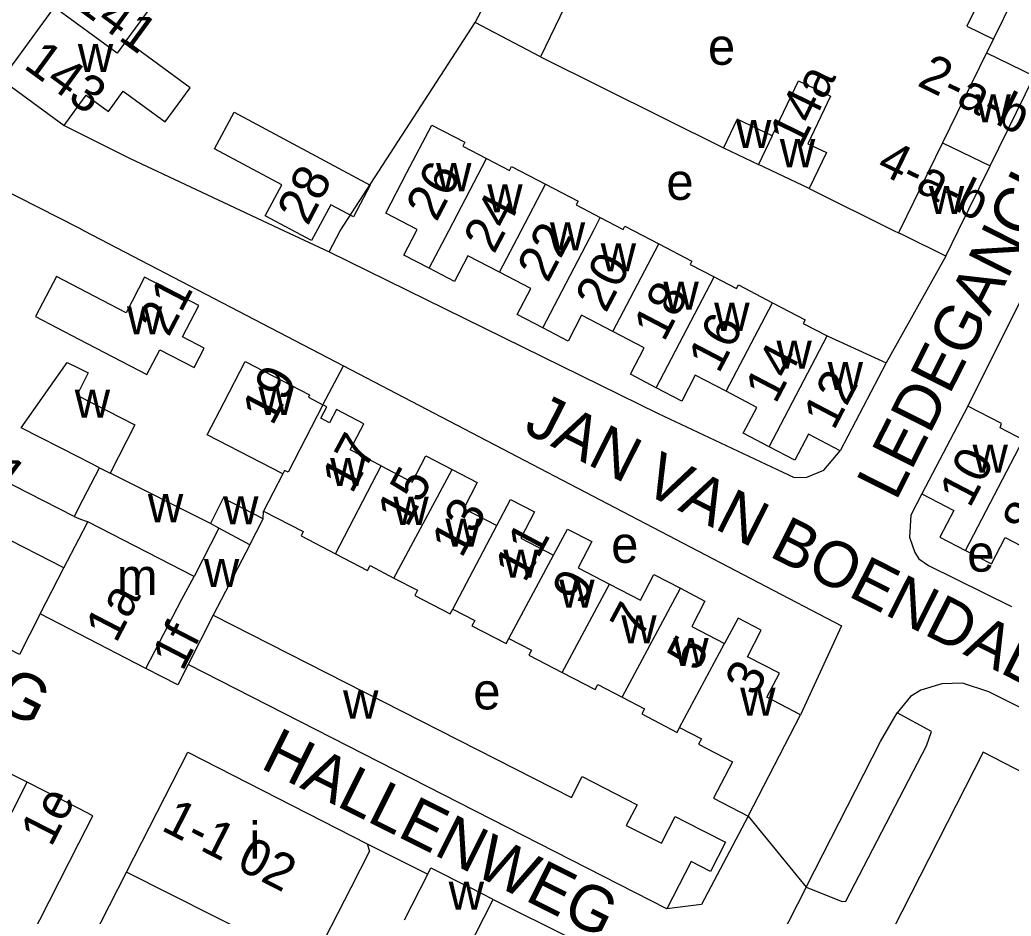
# Model space of a CAD drawing. Extents: x 159700 to 161346, y 381730 to 382922.
# Drawn here: x 160693.5 to 160801.9, y 382358.4 to 382456.4 of the extents above; entities that cross this region are included whole.
import ezdxf

# ---------------------------------------------------------------- set-up
doc = ezdxf.new("R2010")
doc.units = 0
for name, color, linetype in [('BLT_Basislijn', 7, 'Continuous'), ('BLT_Bebouwing', 7, 'Continuous'), ('BLT_Centroide', 7, 'Continuous'), ('BLT_Huisnummer', 7, 'Continuous'), ('BLT_Huisnummer_ tussenligend', 7, 'Continuous'), ('BLT_Huisnummer_reeks', 7, 'Continuous'), ('BLT_Huisnummer_zonder_bebouwing', 7, 'Continuous'), ('BLT_Onderverdeling_panden', 7, 'Continuous'), ('BLT_Plantopo', 7, 'Continuous'), ('BLT_Straatnaam', 7, 'Continuous'), ('BLT_Vlakafsluiter', 7, 'Continuous')]:
    doc.layers.add(name, color=color, linetype=linetype)

msp = doc.modelspace()

# ---------------------------------------------------------------- linework, layer by layer
at = {"layer": 'BLT_Basislijn'}
for p, q in [((160750.48, 382452.35), (160770.5, 382442.41)), ((160689.49, 382438.97), (160700, 382433.64)), ((160794.8, 382430.56), (160788.26, 382418.89)), ((160797.19, 382414.17), (160803.72, 382427.16)), ((160726.67, 382414.31), (160728.93, 382418.55)), ((160728.93, 382418.55), (160783.39, 382390.12)), ((160720.14, 382401.84), (160720.2, 382402.69)), ((160731.53, 382366.3), (160738.15, 382362.99)), ((160779.53, 382361.55), (160773.93, 382350.62)), ((160745.3, 382360.23), (160753.96, 382355.93))]:
    msp.add_line(p, q, dxfattribs=at)
for points in [[(160727.37, 382431.02), (160728.56, 382433.33), (160743.33, 382456.11)], [(160698.39, 382444.84), (160700, 382444.04)], [(160700, 382444.04), (160705.61, 382441.23), (160722.44, 382433.33), (160727.37, 382431.02)], [(160779.87, 382437.96), (160789.14, 382433.33), (160789.62, 382433.1)], [(160700, 382433.64), (160700.59, 382433.33), (160728.93, 382418.55)], [(160727.37, 382431.02), (160763.35, 382413.34), (160778.23, 382406.35), (160779.59, 382406.4), (160781.46, 382407.14), (160783.23, 382409.28)], [(160792.19, 382404.56), (160790.97, 382402.24), (160790.82, 382399.84), (160791.41, 382398.17), (160791.86, 382397.48), (160792.92, 382396.73), (160801.96, 382392.26)], [(160783.39, 382390.12), (160778.92, 382380.42)], [(160856.99, 382352.85), (160808.27, 382378.52), (160799.49, 382382.93), (160796.62, 382383.86), (160794.35, 382383.8), (160792.05, 382383.11), (160790.94, 382382.4), (160789.46, 382380.61)], [(160779.53, 382361.55), (160787.64, 382377.5), (160789.46, 382380.61)], [(160779.53, 382361.55), (160783.45, 382359.98), (160783.86, 382360.02), (160792.69, 382377.02), (160793.22, 382378.6), (160789.46, 382380.61)], [(160773.17, 382369.32), (160768.08, 382359.67), (160764.3, 382359.18)]]:
    msp.add_lwpolyline(points, dxfattribs=at)
at = {"layer": 'BLT_Bebouwing'}
for p, q in [((160705.16, 382454.09), (160708.64, 382458.85)), ((160697.32, 382457.78), (160691.53, 382449.86)), ((160691.53, 382449.86), (160698.39, 382444.84)), ((160698.39, 382444.84), (160700, 382447.05)), ((160705.16, 382424.37), (160700, 382427.06)), ((160695.27, 382423.95), (160700, 382421.49)), ((160700, 382421.49), (160707.43, 382417.63)), ((160788.26, 382418.89), (160783.23, 382409.28)), ((160797.19, 382414.17), (160792.19, 382404.56)), ((160699.5, 382402.09), (160686.2, 382408.86)), ((160702.27, 382407.41), (160700, 382408.56)), ((160700, 382403.06), (160702.27, 382407.41)), ((160722.3, 382406.74), (160720.2, 382402.69)), ((160718.68, 382399.01), (160714.7, 382391.31)), ((160700, 382389.27), (160695.78, 382391.46)), ((160707.33, 382385.48), (160700, 382389.27)), ((160764.3, 382359.18), (160711.94, 382385.9)), ((160694.34, 382373.03), (160687.81, 382376.33)), ((160700, 382370.16), (160694.34, 382373.03)), ((160692.32, 382351.32), (160700, 382366.37)), ((160700, 382353.02), (160705.22, 382363.22)), ((160735.6, 382358), (160738.15, 382362.99)), ((160745.3, 382360.23), (160742.76, 382361.51))]:
    msp.add_line(p, q, dxfattribs=at)
for points in [[(160743.33, 382456.11), (160751.7, 382471.89), (160755.73, 382469.93), (160756.9, 382472.34), (160760.85, 382480.44), (160759.25, 382481.27), (160760.55, 382483.92), (160762.74, 382488.42)], [(160760.83, 382472.98), (160755.64, 382462.85), (160753.02, 382464.26), (160750.95, 382460.38), (160753.64, 382458.93), (160750.48, 382452.35)], [(160797.94, 382461.96), (160799.73, 382461.09), (160797.08, 382455.71), (160800, 382454.28)], [(160750.48, 382452.35), (160743.33, 382456.11)], [(160700, 382447.05), (160700.81, 382448.16), (160703.23, 382446.38), (160704.86, 382448.61), (160709.44, 382445.25), (160712.17, 382448.95), (160705.16, 382454.09)], [(160800, 382454.28), (160799.26, 382452.77)], [(160799.26, 382452.77), (160794.44, 382442.94)], [(160775.81, 382443.7), (160778.68, 382449.72), (160782.18, 382448.06), (160779.71, 382442.85), (160781.74, 382441.88), (160779.87, 382437.96)], [(160799.64, 382440.43), (160804.44, 382450.24)], [(160775.81, 382443.7), (160771.98, 382445.52), (160770.5, 382442.41)], [(160738.31, 382429.23), (160735.54, 382430.68), (160736.93, 382433.33), (160737, 382433.47), (160733.56, 382435.27), (160735.87, 382439.7), (160738.58, 382444.89), (160742.19, 382443), (160741.98, 382442.59), (160744.58, 382441.23)], [(160770.5, 382442.41), (160774.33, 382440.59)], [(160794.44, 382442.94), (160789.74, 382433.33), (160789.62, 382433.1)], [(160744.58, 382441.23), (160747.08, 382439.92), (160747.31, 382440.36), (160751.01, 382438.43)], [(160779.87, 382437.96), (160774.33, 382440.59)], [(160794.8, 382430.56), (160796.16, 382433.33), (160799.64, 382440.43)], [(160751.01, 382438.43), (160754.58, 382436.56), (160754.38, 382436.17), (160757.02, 382434.79)], [(160757.02, 382434.79), (160759.51, 382433.48), (160759.71, 382433.85), (160760.7, 382433.33), (160763.42, 382431.91)], [(160794.8, 382430.56), (160790.31, 382432.76), (160789.62, 382433.1)], [(160763.42, 382431.91), (160767.04, 382430.02), (160766.85, 382429.65), (160769.45, 382428.29)], [(160745.98, 382428.8), (160742.55, 382430.6), (160741.08, 382427.78), (160738.31, 382429.23)], [(160700, 382427.06), (160697.55, 382428.33), (160695.27, 382423.95)], [(160707.43, 382417.63), (160708.84, 382420.33), (160712.61, 382418.37), (160713.71, 382420.49), (160711.34, 382421.72), (160713.13, 382425.16), (160707.18, 382428.26), (160705.16, 382424.37)], [(160750.72, 382422.73), (160747.94, 382424.18), (160749.41, 382427.01), (160745.98, 382428.8)], [(160769.45, 382428.29), (160771.9, 382427.01), (160772.11, 382427.41), (160775.83, 382425.46)], [(160775.83, 382425.46), (160779.41, 382423.59), (160779.2, 382423.2), (160781.81, 382421.84)], [(160758.4, 382422.31), (160754.98, 382424.1), (160753.5, 382421.27), (160750.72, 382422.73)], [(160763.12, 382416.17), (160760.32, 382417.64), (160761.82, 382420.52), (160758.4, 382422.31)], [(160781.81, 382421.84), (160788.26, 382418.89)], [(160700, 382408.56), (160693.7, 382411.77), (160698.73, 382418.94), (160700, 382418.3)], [(160700, 382418.3), (160701.03, 382417.79), (160700, 382415.76)], [(160722.3, 382406.74), (160714.04, 382411.03), (160715.89, 382414.6), (160718.19, 382419.03), (160725.24, 382415.38), (160725.1, 382415.12), (160726.67, 382414.31)], [(160770.77, 382415.78), (160767.4, 382417.54), (160765.93, 382414.71), (160763.12, 382416.17)], [(160700, 382415.76), (160699.79, 382415.35), (160700, 382415.24)], [(160700, 382415.24), (160706.11, 382412.13), (160703.41, 382406.83)], [(160775.47, 382409.71), (160772.65, 382411.19), (160774.13, 382414.02), (160770.77, 382415.78)], [(160733.04, 382407.63), (160729.68, 382409.37), (160731.17, 382412.24), (160728.17, 382413.8), (160727.41, 382412.33), (160726.45, 382412.83), (160727.1, 382414.09), (160726.67, 382414.31)], [(160803.26, 382410.49), (160800.75, 382411.79), (160800.88, 382412.25), (160797.19, 382414.17)], [(160783.23, 382409.28), (160779.78, 382411.09), (160778.29, 382408.24), (160775.47, 382409.71)], [(160733.04, 382407.63), (160736.46, 382405.85), (160737.95, 382408.73), (160740.81, 382407.24)], [(160714.38, 382401.32), (160703.41, 382406.83)], [(160740.81, 382407.24), (160743.56, 382405.82), (160742.09, 382402.97), (160745.69, 382401.1)], [(160720.14, 382401.84), (160715.8, 382404.08), (160714.38, 382401.32)], [(160792.19, 382404.56), (160795.66, 382402.76), (160794.14, 382399.84), (160796.96, 382398.38)], [(160700, 382403.06), (160699.5, 382402.09)], [(160745.69, 382401.1), (160747.21, 382403.94), (160749.81, 382402.59), (160748.33, 382399.73), (160751.91, 382397.87)], [(160720.2, 382402.69), (160724.54, 382400.44), (160724.3, 382399.97), (160728.06, 382398.01)], [(160718.68, 382399.01), (160720.14, 382401.84)], [(160751.91, 382397.87), (160753.43, 382400.71), (160756.08, 382399.34), (160754.6, 382396.47), (160758.03, 382394.69)], [(160796.96, 382398.38), (160799.79, 382396.91), (160801.29, 382399.81), (160804.79, 382397.99)], [(160728.06, 382398.01), (160731.57, 382396.2), (160731.84, 382396.72), (160734.45, 382395.36)], [(160695.78, 382391.46), (160693.52, 382387), (160676.8, 382395.6)], [(160758.03, 382394.69), (160761.42, 382392.93), (160762.88, 382395.74), (160765.77, 382394.24)], [(160734.45, 382395.36), (160737.02, 382394.03), (160736.73, 382393.47), (160740.62, 382391.45), (160740.9, 382391.97)], [(160765.77, 382394.24), (160768.46, 382392.85), (160767.01, 382390.05), (160770.59, 382388.19)], [(160714.7, 382391.31), (160753.88, 382371.37), (160755.03, 382373.65), (160761.05, 382370.58), (160759.85, 382368.32), (160763.71, 382366.36), (160765.2, 382369.3), (160766.26, 382368.76), (160770.72, 382366.49), (160769.08, 382363.27), (160766.94, 382364.36), (160764.3, 382359.18)], [(160740.9, 382391.97), (160743.29, 382390.73), (160742.98, 382390.15), (160746.74, 382388.2), (160747.03, 382388.75)], [(160778.92, 382380.42), (160775.24, 382382.33), (160776.6, 382384.95), (160773.12, 382386.75), (160774.62, 382389.65), (160772.08, 382390.97), (160770.59, 382388.19)], [(160747.03, 382388.75), (160749.48, 382387.47), (160749.2, 382386.92), (160752.86, 382385.02)], [(160711.94, 382385.9), (160710.81, 382383.68), (160707.33, 382385.48)], [(160752.86, 382385.02), (160756.44, 382383.16), (160756.74, 382383.73), (160759.41, 382382.35)], [(160759.41, 382382.35), (160761.85, 382381.08), (160761.55, 382380.5), (160765.41, 382378.49), (160765.69, 382379.03)], [(160773.17, 382369.32), (160778.92, 382380.42)], [(160765.69, 382379.03), (160768.07, 382377.8), (160767.76, 382377.2), (160771.47, 382375.28), (160769.4, 382371.28), (160773.17, 382369.32)], [(160705.22, 382363.22), (160711.92, 382376.33), (160731.53, 382366.3)], [(160809.25, 382370.98), (160798.88, 382376.33), (160788.99, 382356.94)], [(160700, 382366.37), (160701.54, 382369.38), (160700, 382370.16)], [(160731.53, 382366.3), (160731.79, 382365.49), (160729.74, 382361.48), (160725.42, 382353.03)], [(160738.15, 382362.99), (160738.5, 382363.68), (160742.76, 382361.51)], [(160739.85, 382355.82), (160742.37, 382354.51), (160745.3, 382360.23)]]:
    msp.add_lwpolyline(points, dxfattribs=at)
at = {"layer": 'BLT_Onderverdeling_panden'}
for p, q in [((160800, 382454.28), (160806.29, 382467.11)), ((160704.18, 382452.76), (160697.32, 382457.78)), ((160799.26, 382452.77), (160804.44, 382450.24)), ((160775.81, 382443.7), (160774.33, 382440.59)), ((160794.44, 382442.94), (160799.64, 382440.43)), ((160758.4, 382422.31), (160763.42, 382431.91)), ((160763.12, 382416.17), (160769.45, 382428.29)), ((160770.77, 382415.78), (160775.83, 382425.46)), ((160775.47, 382409.71), (160781.81, 382421.84)), ((160796.96, 382398.38), (160803.26, 382410.49)), ((160702.27, 382407.41), (160703.41, 382406.83)), ((160728.06, 382398.01), (160733.04, 382407.63)), ((160734.45, 382395.36), (160740.81, 382407.24)), ((160698.37, 382396.46), (160681.66, 382405.05)), ((160699.5, 382402.09), (160700, 382401.89)), ((160700, 382401.89), (160700.98, 382401.5)), ((160700, 382399.6), (160700.98, 382401.5)), ((160712.61, 382395.52), (160700.98, 382401.5)), ((160715.32, 382400.81), (160714.38, 382401.32)), ((160740.9, 382391.97), (160745.69, 382401.1)), ((160715.32, 382400.81), (160712.61, 382395.52)), ((160718.68, 382399.01), (160715.32, 382400.81)), ((160698.37, 382396.46), (160700, 382399.6)), ((160747.03, 382388.75), (160751.91, 382397.87)), ((160695.78, 382391.46), (160698.37, 382396.46)), ((160711.25, 382393.07), (160712.61, 382395.52)), ((160752.86, 382385.02), (160758.03, 382394.69)), ((160759.41, 382382.35), (160765.77, 382394.24)), ((160707.33, 382385.48), (160711.25, 382393.07)), ((160714.7, 382391.31), (160711.94, 382385.9)), ((160765.69, 382379.03), (160770.59, 382388.19)), ((160685.19, 382354.97), (160694.34, 382373.03)), ((160725.42, 382353.03), (160705.22, 382363.22))]:
    msp.add_line(p, q, dxfattribs=at)
for points in [[(160705.16, 382454.09), (160704.18, 382452.76)], [(160738.31, 382429.23), (160740.45, 382433.33), (160744.58, 382441.23)], [(160745.98, 382428.8), (160748.35, 382433.33), (160751.01, 382438.43)], [(160750.72, 382422.73), (160756.26, 382433.33), (160757.02, 382434.79)], [(160726.67, 382414.31), (160722.89, 382406.92), (160722.5, 382407.12), (160722.3, 382406.74)]]:
    msp.add_lwpolyline(points, dxfattribs=at)
at = {"layer": 'BLT_Plantopo'}
msp.add_lwpolyline([(160716.98, 382446.28), (160731.87, 382438.3), (160730.02, 382434.86), (160727.54, 382436.18), (160725.45, 382432.27), (160720.39, 382434.98), (160722.2, 382438.36), (160714.85, 382442.29)], close=True, dxfattribs=at)
at = {"layer": 'BLT_Vlakafsluiter'}
msp.add_line((160773.17, 382369.32), (160779.53, 382361.55), dxfattribs=at)

# ---------------------------------------------------------------- texts
at = {"layer": 'BLT_Centroide'}
for s, p in [('e', (160768.79, 382451.48)), ('w', (160699.89, 382450.69)), ('w', (160798.04, 382445.17)), ('w', (160771.85, 382442.37)), ('w', (160776.65, 382440.28)), ('w', (160739.06, 382437.66)), ('e', (160764.24, 382436.71)), ('w', (160744.66, 382435.34)), ('w', (160792.94, 382435.16)), ('w', (160751.5, 382431.19)), ('w', (160757.06, 382428.88)), ('w', (160763.92, 382424.69)), ('w', (160705.26, 382422)), ('w', (160769.47, 382422.38)), ('w', (160776.28, 382418.25)), ('w', (160781.88, 382415.91)), ('w', (160719.64, 382413.2)), ('w', (160699.55, 382412.88)), ('w', (160797.72, 382406.88)), ('w', (160727.48, 382405.41)), ('w', (160707.55, 382401.47)), ('w', (160715.78, 382401.24)), ('w', (160734.38, 382401.17)), ('w', (160740.08, 382398.8)), ('e', (160758.21, 382397.03)), ('e', (160797.14, 382396.06)), ('w', (160746.41, 382395.41)), ('m', (160704.16, 382393.5)), ('w', (160713.68, 382394.39)), ('w', (160752.53, 382392.11)), ('w', (160759.31, 382388.22)), ('w', (160765, 382385.75)), ('e', (160743.13, 382381)), ('w', (160728.89, 382380)), ('w', (160772.31, 382380.31)), ('i', (160718.66, 382364.69)), ('w', (160740.44, 382359.09))]:
    msp.add_text(s, height=4, dxfattribs=at).set_placement(p)
at = {"layer": 'BLT_Huisnummer'}
for s, rotation, p in [('143', 323.7907, (160693.84, 382451.19)), ('14a', 63.8824, (160778.91, 382442.17)), ('26', 62.4083, (160739.11, 382434.2)), ('20', 62.4076, (160757.63, 382424.24)), ('21', 62.574, (160709.82, 382421.62)), ('16', 62.4053, (160769.97, 382417.61)), ('151-151 01', 322.8555, (160670.68, 382420.42)), ('19', 62.5752, (160721.18, 382411.9)), ('12', 62.4098, (160782.55, 382411.4)), ('17', 61.838, (160729.87, 382404.46)), ('10', 62.5338, (160797.42, 382402.92)), ('15', 61.8431, (160735.92, 382400.78)), ('8', 62.528, (160804.31, 382399.76)), ('11', 61.8393, (160748.79, 382394.74)), ('1a', 62.6353, (160704.08, 382388.14)), ('7', 61.8391, (160761.42, 382388.58)), ('1f', 62.6353, (160711.34, 382385.06)), ('3', 62.5735, (160774, 382382.29)), ('1e', 62.9555, (160696.98, 382365.85))]:
    msp.add_text(s, height=4, rotation=rotation, dxfattribs=at).set_placement(p)
at = {"layer": 'BLT_Huisnummer_ tussenligend'}
for s, rotation, p in [('141', 323.7853, (160699.41, 382457.82)), ('24', 62.4071, (160745.41, 382430.69)), ('22', 62.4076, (160751.28, 382427.52)), ('18', 62.4053, (160763.98, 382421.07)), ('14', 62.4098, (160776.19, 382414.3)), ('13', 61.8393, (160741.86, 382397.43)), ('9', 61.8391, (160755.07, 382392.22)), ('5', 62.5735, (160767.65, 382385.01))]:
    msp.add_text(s, height=4, rotation=rotation, dxfattribs=at).set_placement(p)
at = {"layer": 'BLT_Huisnummer_reeks'}
for s, rotation, p in [('2-a-b', 333.8911, (160791.55, 382449.26)), ('4-a-b', 333.8882, (160787.06, 382439.82)), ('1-1 02', 332.9209, (160708.88, 382367.86))]:
    msp.add_text(s, height=4, rotation=rotation, dxfattribs=at).set_placement(p)
at = {"layer": 'BLT_Huisnummer_zonder_bebouwing'}
msp.add_text('28', height=4, rotation=62.4083, dxfattribs=at).set_placement((160725.03, 382433.77))
at = {"layer": 'BLT_Straatnaam'}
for s, rotation, p in [('LEDEGANCKSTRAAT', 63.2992, (160789.34, 382403.68)), ('JAN VAN BOENDALELAAN', 333.212, (160748.48, 382411.37)), ('HALLENWEG', 333.1464, (160657.75, 382398)), ('HALLENWEG', 333.4315, (160719.73, 382374.66))]:
    msp.add_text(s, height=5, rotation=rotation, dxfattribs=at).set_placement(p)

doc.saveas('drawing.dxf')
